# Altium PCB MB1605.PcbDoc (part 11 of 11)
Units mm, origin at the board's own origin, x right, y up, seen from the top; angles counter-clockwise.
Board outline 100 x 79.6 mm, 6 copper layers (Top Layer, Signal Layer 1, Signal Layer 2, Signal Layer 3, Signal Layer 4, Bottom Layer), stack 1.549 mm thick; 644 components, 529 nets, 2853 pads, 1462 vias.
Unrouted connection lines stored in the file: 2.
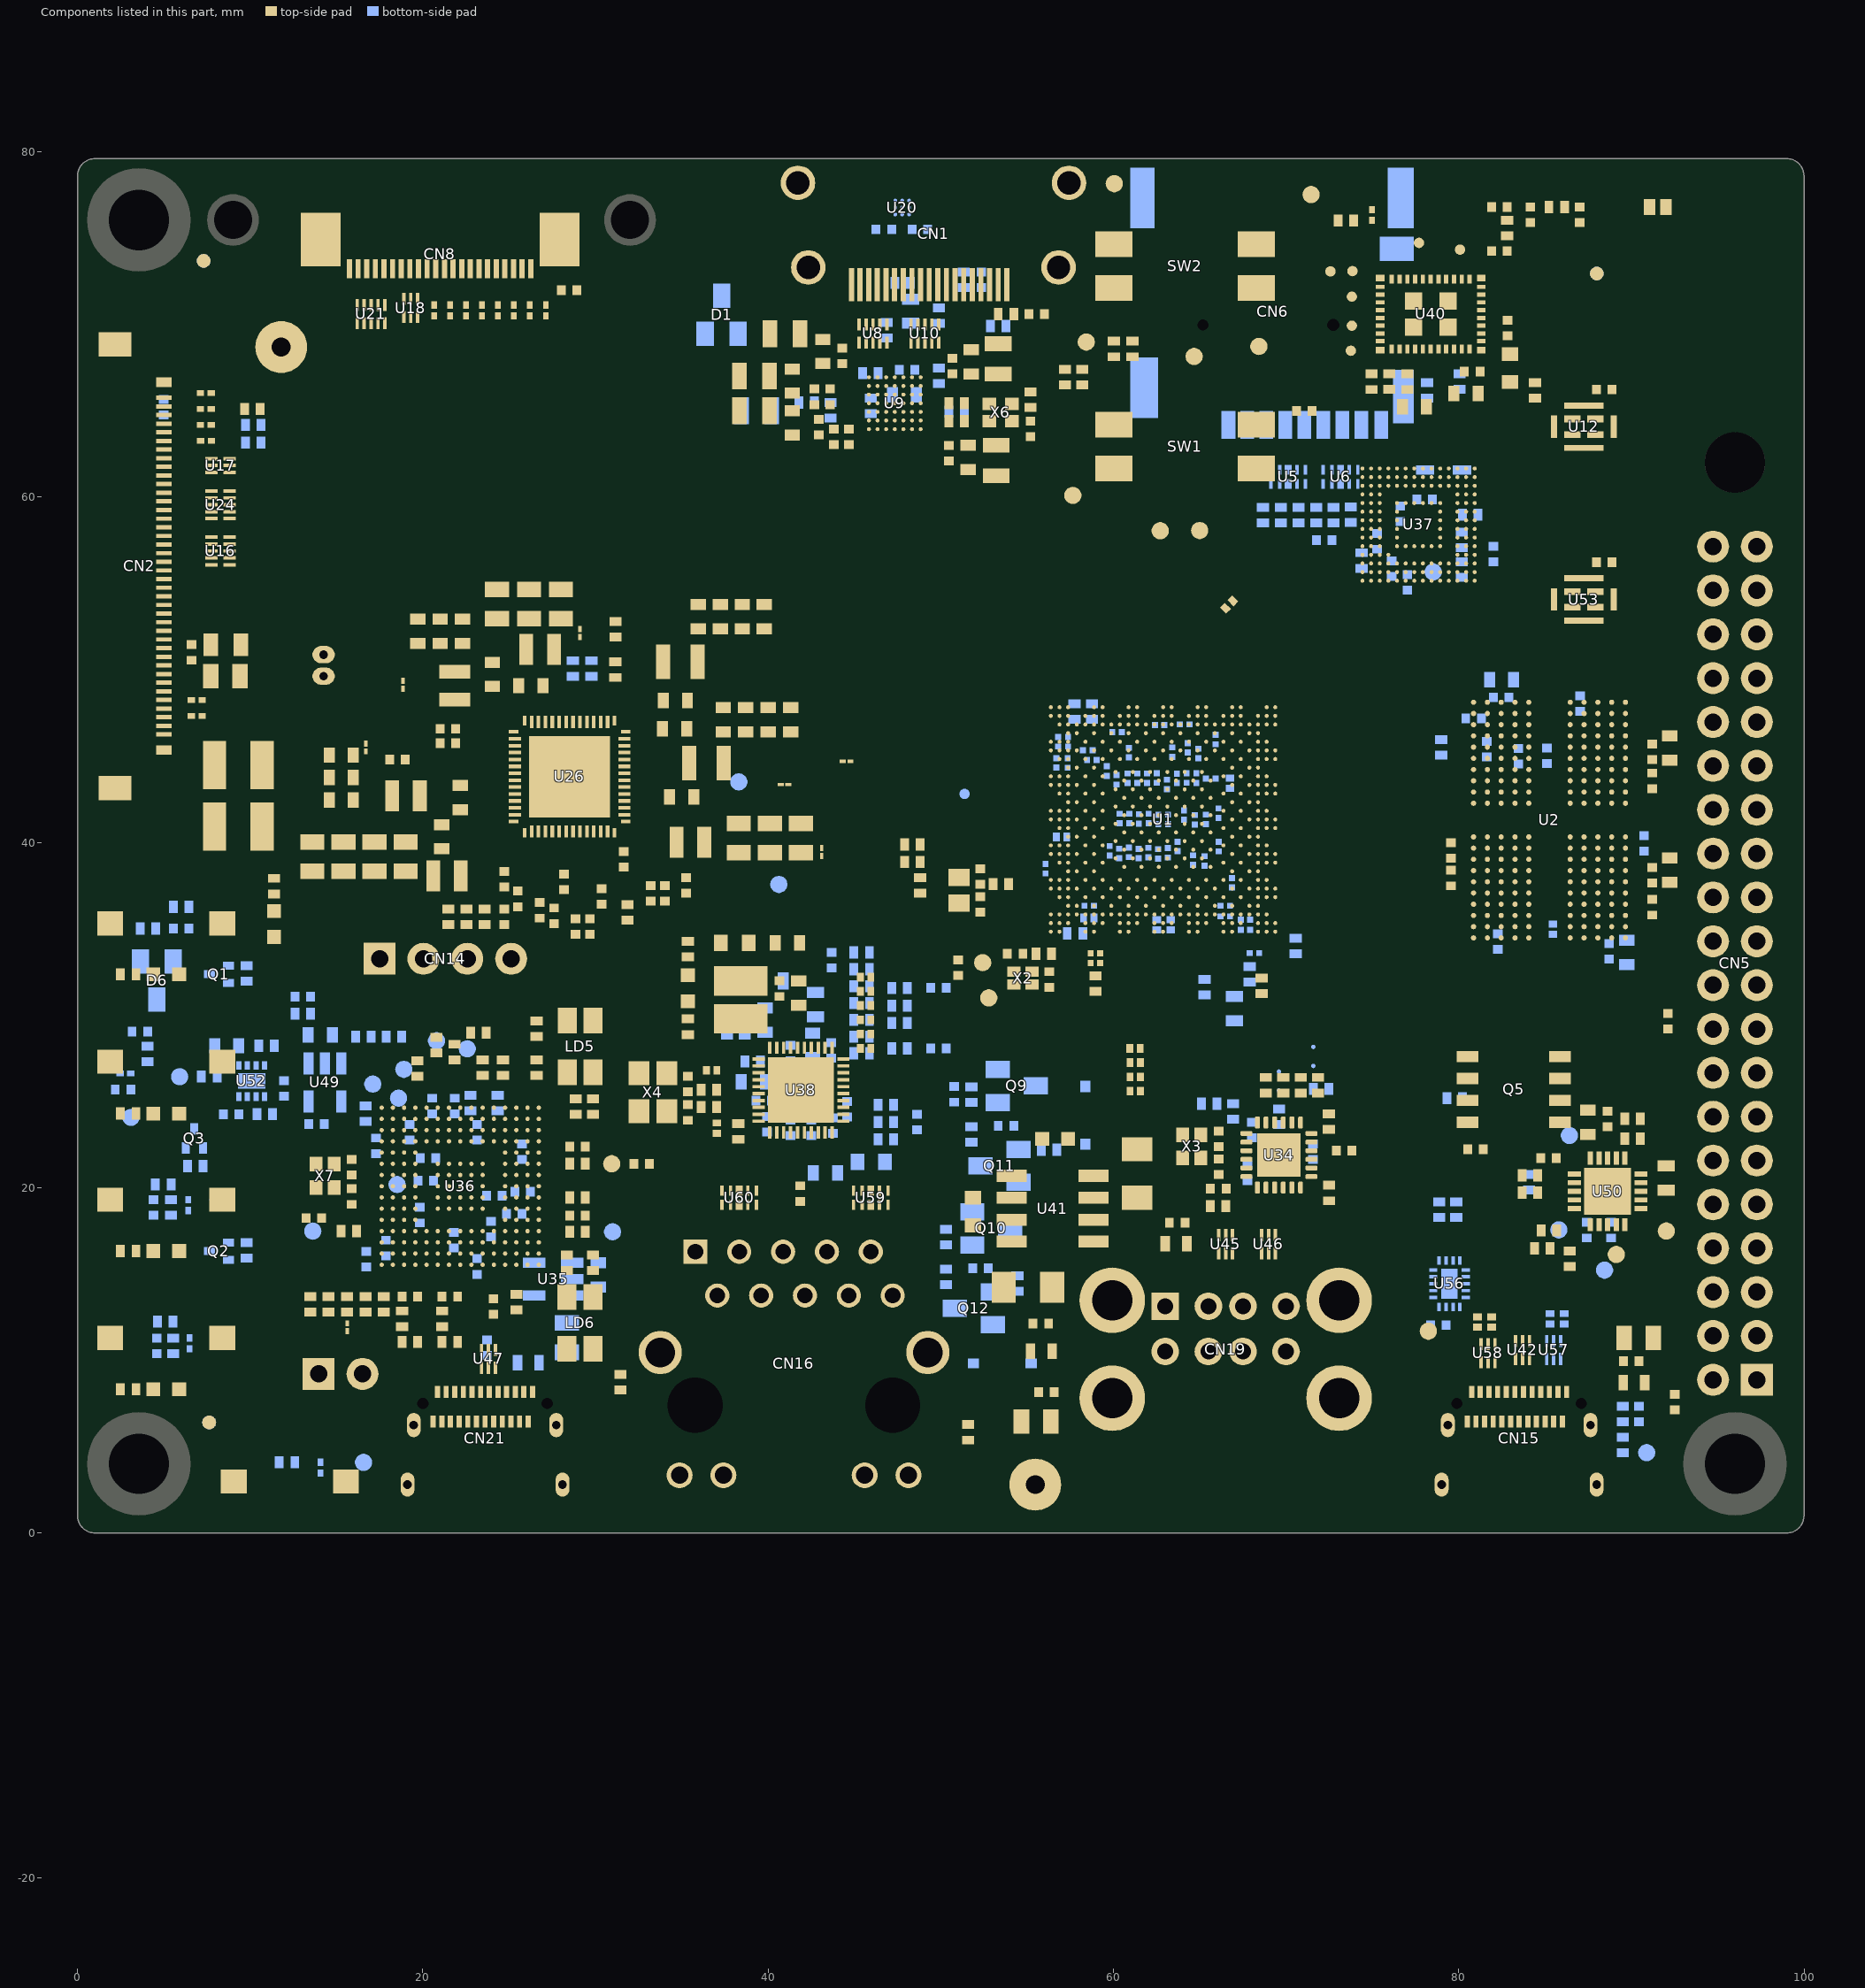
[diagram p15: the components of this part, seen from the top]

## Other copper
Top Layer:
  rectangle net 5V_STLK: 9.039,50.774 10.264,52.124
  rectangle net GND: 9.414,48.925 10.264,50.325
  rectangle net VDD2_DDR: 15.655,41.8 18.625,43.6
  region net 5V_STLK: 86.495,22.224 86.495,25.487 82.045,25.487 82.045,22.224
  region net 5V_STLK: 55.12,5.756 55.12,7.156 52.72,7.156 52.72,5.756
  region net NetL1_1: 27.572,49.875 ccw(c27.269,49.883) 27.478,50.102 27.455,50.125 27.455,50.187 27.526,50.194 ccw(c27.525,50.194) 27.525,50.195 27.675,50.075
  region net GND: 32.225,44 32.15,43.925 32.072,43.925 cw(c32.072,43.798) 32.162,43.888 32.188,43.862 ccw(c32.278,43.952) 32.278,43.825 32.947,43.825 cw(c32.947,43.698) 33.037,43.788 33.1,43.725 33.229,43.854 cw(c33.28,43.803) 33.28,43.875
  region net 5V_STLK: 33.605,47.78 33.43,47.672 ccw(c33.563,47.473) 33.394,47.642 33.353,47.601 ccw(c33.613,47.342) 33.246,47.342 33.246,47.326 ccw(c33.601,47.326) 33.35,47.075 33.35,45.539 33.349,45.538 33.347,45.551 32.876,45.08 32.27,45.08 32.27,45.345 32.506,45.345 32.98,45.819 32.98,48.347 33.308,48.67 34.325,48.67 34.325,47.78
  region net 5V_STLK: 25.23,48.524 25.131,48.425 24.775,48.425 cw(c24.775,48.775) 24.425,48.775 24.425,48.825 23.7,48.825 ccw(c23.7,48.75) 23.625,48.75 23.625,48.4 ccw(c23.827,48.397) 23.825,48.195 26.45,48.195 26.85,47.8 27.112,47.8 26.391,48.521 26.125,48.525
  region net GND: 24.9,47.685 24.807,47.685 ccw(c24.807,47.584) 24.735,47.655 24.455,47.375 ccw(c24.526,47.303) 24.425,47.303 24.425,46.975 24.925,46.975 cw(c25.323,46.982) 25.315,47.38 25.575,47.375 ccw(c25.575,47.423) 25.609,47.389 25.705,47.485
  region: 99,66.175 ccw(c99.05,66.175) 99.05,66.125 99.45,66.125 ccw(c99.45,66.175) 99.5,66.175 99.5,77.075 ccw(c99.45,77.075) 99.45,77.125 91.875,77.125 91.875,76.625 99,76.625
  pour cut-out: 90,78.05 cw(c89.925,78.05) 89.925,77.975 82.8,77.975 ccw(c82.8,76.8) 81.625,76.8 81.625,73.8 cw(c81.55,73.8) 81.55,73.725 81.075,73.725 ccw(c81.075,73.575) 80.925,73.575 80.925,71.075 ccw(c81,71.075) 81,71 81.904,71 ccw(c81.904,73.072) 83.975,73.072 83.975,75.494 cw(c84.106,75.494) 84.106,75.625 89.925,75.625 cw(c89.925,75.55) 90,75.55 90,65.6 101.05,65.6 101.05,80 90,80
  pour cut-out: 70.033,46.694 74.981,51.642 87.419,51.642 90.759,48.302 90.759,33.774 86.353,29.368 75.322,29.368 69.961,34.644
  pour cut-out: 45.292,67.365 49.286,67.365 49.286,63.578 45.292,63.578
  pour cut-out: 74.075,62 81.35,62 81.35,54.798 74.075,54.798
  pour cut-out: 80.525,48.72 90.26,48.72 90.26,34.328 80.525,34.328
  pour cut-out: 55.55,48.775 69.762,48.775 69.762,34.3 55.55,34.3
  pour cut-out: 17.29,24.95 27.025,24.95 27.025,15.175 17.29,15.175
  region net GND: 39,41.298 39,42.651 37.6,42.651 37.6,41.298
  region net GND: 40.8,41.298 40.8,42.651 39.4,42.651 39.4,41.298
  region net GND: 42.6,41.298 42.6,42.651 41.2,42.651 41.2,41.298
  pour cut-out: 40.075,31.025 40.075,30.725 36.85,30.725 36.85,31.05
  region net NetQ5_7: 82.045,25.887 82.045,28.387 91.336,28.387 93.46,26.262 93.46,20.94 91.525,20.94 91.525,22.442 91.617,22.534 91.617,24.297 90.027,25.887
  region net GND: 36.502,42.375 36.307,42.18 36,42.18 36,43.07 36.475,43.07 36.67,42.875 36.67,42.375
  region net GND: 36.325,47.975 36.13,47.78 35.275,47.78 35.275,48.67 36.13,48.67 36.325,48.475
  region net GND: 24.275,51.373 24.47,51.178 24.47,50.723 23.58,50.723 23.58,51.178 23.775,51.373
  region net GND: 36.3,46.325 36.105,46.13 35.25,46.13 35.25,47.02 36.105,47.02 36.3,46.825
  region net GND: 37.65,48.825 37.845,48.63 37.845,47.775 36.955,47.775 36.955,48.63 37.15,48.825
  region net GND: 38.95,48.825 39.145,48.63 39.145,47.775 38.255,47.775 38.255,48.63 38.45,48.825
  region net GND: 40.25,48.825 40.445,48.63 40.445,47.775 39.555,47.775 39.555,48.63 39.75,48.825
  region net GND: 41.55,48.825 41.745,48.63 41.745,47.775 40.855,47.775 40.855,48.63 41.05,48.825
  region net VDDIO: 41.58,38.835 41.58,38.719 41.227,38.366 41.227,37.235 41.58,37.235 42.22,37.235 42.577,37.235 42.577,38.431 42.22,38.788 42.22,39.212 41.58,39.212
  region net 5V_STLK: 20.075,39.948 20.725,39.948 20.725,39.305 20.42,39.305 20.325,39.4 20.075,39.4
  region net GND: 19.025,40.798 19.175,40.648 19.175,40.398 18.3,40.398 18.3,40.823 18.525,41.048 19.025,41.048
  region net GND: 19.025,40.798 18.875,40.648 18.875,40.398 19.7,40.398 19.7,40.873 19.525,41.048 19.025,41.048
  region net GND: 17.225,40.798 17.375,40.648 17.375,40.398 16.5,40.398 16.5,40.823 16.725,41.048 17.225,41.048
  region net GND: 17.225,40.798 17.075,40.648 17.075,40.398 17.9,40.398 17.9,40.873 17.725,41.048 17.225,41.048
  region net GND: 15.425,40.798 15.575,40.648 15.575,40.398 14.7,40.398 14.7,40.823 14.925,41.048 15.425,41.048
  region net GND: 15.425,40.798 15.275,40.648 15.275,40.398 16.1,40.398 16.1,40.873 15.925,41.048 15.425,41.048
  region net GND: 13.625,40.798 13.775,40.648 13.775,40.398 12.9,40.398 12.9,40.823 13.125,41.048 13.625,41.048
  region net GND: 13.625,40.798 13.475,40.648 13.475,40.398 14.3,40.398 14.3,40.873 14.125,41.048 13.625,41.048
  region net GND: 20.075,40.75 20.12,40.705 20.68,40.705 20.725,40.75 20.725,41.345 20.42,41.345 20.325,41.25 20.075,41.25
  region net 5V_STLK: 23.25,43.62 23.25,43.4 22.83,42.98 21.15,42.98 21.15,43.525 21.4,43.525 21.495,43.62
  region net GND: 21.925,40.952 21.73,41.147 21.73,41.602 22.62,41.602 22.62,41.147 22.425,40.952
  region net 5V_STLK: 27.175,49.85 27.27,49.755 27.27,49.45 26.63,49.45 26.63,49.805 26.675,49.85 26.675,50.1 27.175,50.1
  region net GND: 24.6,49.323 24.797,49.52 25.25,49.52 25.25,48.63 24.793,48.63 24.6,48.823
  region net VDD2_DDR: 16.295,45.615 16.295,45.731 16.648,46.084 16.648,47.215 16.295,47.215 15.655,47.215 15.298,47.215 15.298,46.019 15.655,45.662 15.655,45.238 16.295,45.238
  region net GND: 13.6,42.7 13.795,42.895 14.575,42.895 14.575,42.005 13.795,42.005 13.6,42.2
  region net GND: 13.6,44 13.795,44.195 14.575,44.195 14.575,43.305 13.795,43.305 13.6,43.5
  region net GND: 13.6,45.3 13.795,45.495 14.575,45.495 14.575,44.605 13.795,44.605 13.6,44.8
  region net GND: 22.55,53.873 22.745,53.678 22.745,53.223 21.855,53.223 21.855,53.678 22.05,53.873
  region net GND: 21.25,53.873 21.445,53.678 21.445,53.223 20.555,53.223 20.555,53.678 20.75,53.873
  region net GND: 19.95,53.873 20.145,53.678 20.145,53.223 19.255,53.223 19.255,53.678 19.45,53.873
  region net GND: 40.025,54.825 40.22,54.63 40.22,53.775 39.33,53.775 39.33,54.63 39.525,54.825
  region net GND: 38.75,54.825 38.945,54.63 38.945,53.775 38.055,53.775 38.055,54.63 38.25,54.825
  region net GND: 37.475,54.825 37.67,54.63 37.67,53.775 36.78,53.775 36.78,54.63 36.975,54.825
  region net GND: 36.2,54.825 36.395,54.63 36.395,53.775 35.505,53.775 35.505,54.63 35.7,54.825
  region net GND: 24.325,55.425 24.475,55.275 24.475,55.025 23.6,55.025 23.6,55.45 23.825,55.675 24.325,55.675
  region net GND: 24.325,55.425 24.175,55.275 24.175,55.025 25,55.025 25,55.5 24.825,55.675 24.325,55.675
  region net GND: 26.175,55.425 26.025,55.275 26.025,55.025 26.85,55.025 26.85,55.5 26.675,55.675 26.175,55.675
  region net GND: 26.175,55.425 26.325,55.275 26.325,55.025 25.45,55.025 25.45,55.45 25.675,55.675 26.175,55.675
  region net GND: 28.025,55.425 27.875,55.275 27.875,55.025 28.7,55.025 28.7,55.5 28.525,55.675 28.025,55.675
  region net GND: 28.025,55.425 28.175,55.275 28.175,55.025 27.3,55.025 27.3,55.45 27.525,55.675 28.025,55.675
  region net NetL2_1: 33.65,50.225 33.65,49.45 33.515,49.45 32.825,48.76 32.825,46 32.35,45.525 32.025,45.525 32.025,45.675 32.114,45.675 32.27,45.831 32.45,46.011 32.505,46.094 32.525,46.191 32.525,46.742 32.57,46.85 32.57,47.01 32.509,47.157 32.397,47.269 32.27,47.322 32.25,47.325 32.25,51.102 32.598,51.45 33.515,51.45 33.65,51.315 33.65,51.2
  region net NetL4_1: 34.525,45.6 34.525,43.6 35.434,43.6 35.434,45.6
  region net NetL3_1: 22.575,46.975 21.388,48.162 22.488,48.162 22.575,48.075 26.18,48.075 26.42,47.835 24.79,47.835 24.768,47.833 24.748,47.829 24.72,47.82 24.701,47.813 24.675,47.799 24.658,47.788 24.635,47.769 24.341,47.474 24.322,47.452 24.311,47.435 24.302,47.419 24.29,47.39 24.286,47.378 24.281,47.362 24.277,47.342 24.276,47.327 24.274,47.313 24.274,46.975
  region net NetL3_1: 23.783,48.045 23.754,48.048 23.725,48.057 23.651,48.089 23.625,48.103 23.603,48.122 23.547,48.18 23.528,48.203 23.514,48.229 23.488,48.294 23.481,48.316 23.458,48.347 23.433,48.367 23.397,48.391 23.351,48.4 22.575,48.4 22.575,47.263
  region net NetL7_1: 22.875,38.35 22.575,38.05 21.8,38.05 21.8,38.95 22.875,40.02
  region net NetL1_1: 27.995,50.275 27.65,49.93 27.195,50.385 27.195,52.075 27.995,52.075
  region net NetL5_1: 19.425,43.948 19.65,44.173 21.025,44.173 21.025,42.323 20.502,41.8 20.225,41.8 19.425,41.8
  region net 5V_STLK: 34.125,45.25 33.55,44.675 32.875,44.675 32.875,44.85 33.4,45.375
  region net GND: 32.83,44.125 33.28,44.125 33.28,43.825 33.155,43.7 32.98,43.875 32.83,43.875
  region net 5V_STLK: 34.075,41.85 33.977,41.948 33.977,42.625 34.62,42.625 34.62,41.895 34.575,41.85 34.575,41.6 34.075,41.6
  region net 5V_STLK: 34.075,41.875 34.075,42.125 33.175,43.025 33.925,43.025 34.247,42.703
  region net 5V_STLK: 34.195,46.175 34.195,45.32 34.125,45.25 34,45.375 33.4,45.375 33.555,45.53 33.555,46.175
  pour cut-out: 42.6,39.925 37.63,39.925 37.63,40.575 42.6,40.575
  pour cut-out: 12.9,38.773 19.55,38.773 19.55,39.573 12.9,39.573
  region net 5V_STLK: 34.175,49 34.325,48.85 34.325,48.6 33.525,48.6 33.525,48.85 33.675,49 33.675,49.25 34.175,49.25
  region net 5V_STLK: 23.25,49.3 23.295,49.345 23.65,49.345 23.65,48.65 23.4,48.65 23.25,48.8 23,48.8 23,49.3
  region net GND: 31.921,46.656 32.02,46.656 32.049,46.653 32.078,46.644 32.104,46.63 32.127,46.612 32.145,46.589 32.17,46.555 32.17,46.23 32.27,46.23 32.27,46.93 31.921,46.93
  region net 5V_STLK: 27.425,47.725 27.4,47.725 26.63,48.495 26.63,48.825 27.27,48.825 27.27,48.605 27.4,48.475 27.4,47.925
  region net GND: 25.575,47.375 25.24,47.375 25.24,47.385
  pour cut-out: 35.9,41.075 35.1,41.075 35.1,38.975 35.9,38.975
  pour cut-out: 36.955,45.45 35.895,45.45 35.895,43.35 36.955,43.35
  pour cut-out: 35.445,51.25 34.385,51.25 34.385,49.15 35.445,49.15
  pour cut-out: 21.94,39.1 20.88,39.1 20.88,37 21.94,37
  pour cut-out: 27.155,52.225 26.435,52.225 26.435,50.125 27.155,50.125
  pour cut-out: 20.8,49.605 20.8,48.545 22.9,48.545 22.9,49.605
  pour cut-out: 21.5,40.6 19.55,40.6 19.55,40.025 21.5,40.025
  region net 5V_STLK: 22.875,40.9 22.716,40.9 22.689,40.874 22.648,40.842 22.602,40.815 22.554,40.795 22.503,40.782 22.451,40.775 22.425,40.774 21.925,40.774 21.899,40.775 21.847,40.782 21.796,40.795 21.748,40.815 21.702,40.842 21.661,40.874 21.65,40.45 21.65,39.945 21.375,39.945 21.375,39.305 21.83,39.305 22.599,40.074 22.599,40.184 22.603,40.227 22.613,40.27 22.629,40.31 22.652,40.346 22.68,40.379 23.038,40.737
  pour cut-out: 18.495,41.65 19.555,41.65 19.555,43.75 18.495,43.75
  pour cut-out: 35.855,40.875 37.63,40.875 37.63,39.6 36.3,39.6
  region net 5V_STLK: 34.125,47.35 34.275,47.2 34.275,46.95 33.475,46.95 33.475,47.2 33.625,47.35 33.625,47.6 34.125,47.6
  text "1" at 1.614,70.692 h2
Signal Layer 1:
  text "2" at 2.9,70.692 h2
Signal Layer 2:
  text "3" at 4.406,70.703 h2
Signal Layer 3:
  text "4" at 6.769,70.694 h2
Signal Layer 4:
  text "5" at 8.249,70.713 h2
Bottom Layer:
  pour cut-out: 76.092,40.03 76.093,40.029 76.093,31.983 79.372,28.704 79.398,28.729 95.509,28.729 98.821,32.041 98.812,32.05 98.812,37.325 97.242,38.896 86.519,38.896 83.809,41.606 77.671,41.606 76.093,40.028
  region net 5V_STLK: 9.986,26.827 9.186,26.827 9.186,27.922 9.016,28.092 9.016,30.012 10.936,30.012 10.936,29.592 10.566,29.222 9.986,28.642
  region net VBUS_STLK: 10.286,22.707 10.286,23.099 9.986,23.399 9.986,25.527 9.186,25.527 9.186,23.886 8.421,23.121 8.421,22.729 9.126,22.024 9.603,22.024
  text "6" at 9.748,70.702 h2

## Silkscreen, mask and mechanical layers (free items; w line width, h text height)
Top Overlay:
  lines w0.15: 11.334,29.846 11.334,29.518 11.547,29.305 19.167,29.305 19.698,28.774 19.698,28.351 ; 35.752,26.883 35.94,27.259 ; 35.779,21.512 36.182,24.097 ; 49.675,62.725 49.675,64.55 50.025,64.9
  text "BOOT3" at 68.063,75.618 h1.2
  text "HDMI" at 36.968,75.21 h2
  text "CSI" at 29.699,72.452 h2
  text "GND" at 10.739,70.565 h1.2
  text "BOOT2" at 68.089,69.878 h1.2
  text "BOOT1" at 68.034,65.693 h1.2
  text "J" at 20.837,60.494 h15
  text "MB1605C" at 19.907,58.875 h3
  text "BOOT0" at 67.488,58.48 h1.2
  text "I" at 11.65,56.115 h15
  text "G" at 33.288,55.556 h11
  text "E" at 44.597,52.495 h12
  text "H" at 44.461,45.08 h15
  text "F" at 71.3,42.158 h12
  text "LVDS" at 1.176,40.909 h2
  text "WAKE UP" at 1.063,37.75 h2
  text "RESERVED" at 15.964,30.434 h2
  text "TAMPER" at 1.34,29.563 h2
  text "C" at 70.691,29.487 h11
  text "COM" at 32.263,28.177 h2 r90
  text "USER2" at 2.272,21.666 h2
  text "USER1" at 2.142,13.697 h2
  text "PWR" at 32.19,10.17 h2 r90
  text "RESET" at 9.548,5.243 h2
  text "GND" at 53.71,1.714 h1.2 r90
  text "USB" at 59.366,1.505 h2 r90
  text "ETH" at 51.79,1.405 h2 r90
  text "USB DRD" at 78.165,0.395 h2 r90
  text "USB PWR / STLNK" at 31.533,0.355 h2 r90
Bottom Overlay:
  lines w0.15: 57.925,42.3 58.15,42.525 58.15,44.475
Top Solder:
  region: 1.325,72.334 1.325,70.334 10.075,70.334 10.075,72.334
Bottom Solder:
  region: 1.325,72.334 1.325,70.334 10.075,70.334 10.075,72.334
M1-Board Shape:
  the board outline again, w0.02
Drill Drawing:
  drawing of 358 lines, arcs and shapes, not listed
  text "Layer" at 122.2,127.475 h2
  text "Name" at 130.567,127.475 h2
  text "Material" at 146.741,127.475 h2
  text "Thickness" at 161.275,127.475 h2
  text "Constant" at 173.215,127.475 h2
  text "PCB SPECIFICATIONS :" at -27.02,127.275 h3
  text "Top Overlay" at 130.567,123.475 h2
  text "A.   MATERIAL :" at -27.02,123.275 h3
  text "FR-4" at 11.48,123.275 h3
  text "TG-170" at 27.98,123.275 h3
  text "X  TG-150" at 46.23,123.275 h3
  text "TG-140" at 62.23,123.275 h3
  text "B.   MATERIAL FAMILY :" at -27.02,120.275 h3
  text "N/A" at 11.48,120.275 h3
  text "Top Solder" at 130.567,119.475 h2
  text "Solder Resist" at 146.741,119.475 h2
  text "0,025mm" at 161.275,119.475 h2
  text "3.5" at 173.215,119.475 h2
  text "C.   SOLDERMASK COLOR :" at -27.02,117.275 h3
  text "GREEN" at 11.48,117.275 h3
  text "X  BLUE" at 27.98,117.275 h3
  text "RED" at 46.23,117.275 h3
  text "BLACK" at 62.23,117.275 h3
  text "1" at 122.2,115.475 h2
  text "Top Layer" at 130.567,115.475 h2
  text "0,037mm" at 161.275,115.475 h2
  text "D.   SILKSCREEN COLOR :" at -27.02,114.275 h3
  text "X  WHITE" at 11.48,114.275 h3
  text "YELLOW" at 27.98,114.275 h3
  text "BLACK" at 46.23,114.275 h3
  text "PCB : TYPE 4" at 187.138,113.471 h3
  text "Dielectric 1" at 130.567,111.475 h2
  text "0,072mm" at 161.275,111.475 h2
  text "3.8" at 173.215,111.475 h2
  text "E.   SURFACE FINISH :" at -27.02,111.275 h3
  text "X  ENIG" at 11.48,111.275 h3
  text "IMMERSION SILVER" at 27.98,111.275 h3
  text "IMMERSION TIN" at 62.23,111.275 h3
  text "HASL" at 11.48,108.275 h3
  text "HASL (PB-FREE)" at 27.98,108.275 h3
  text "GOLDEN FINGER" at 62.23,108.275 h3
  text "ASPECT-RATIO, AXE Z :" at 187.138,107.971 h3
  text "2" at 122.199,107.475 h2
  text "Signal Layer 1" at 130.567,107.475 h2
  text "0,035mm" at 161.275,107.475 h2
  text "F.   IMPEDANCE CONTROL :" at -27.02,105.275 h3
  text "NO" at 11.48,105.275 h3
  text "X  YES" at 27.98,105.275 h3
  text "Dielectric 2" at 130.567,103.475 h2
  text "0,500mm" at 161.275,103.475 h2
  text "5" at 173.215,103.475 h2
  text "G.   THROUGH VIA :" at -27.02,102.275 h3
  text "PLUG THE VIAS WHICH ARE COVERED WITH SOLDERMASK ONE OR TWO SIDE." at 11.48,102.275 h3
  text "6 :1  to  8 :1 / LEVEL \"B\"" at 187.157,101.224 h3
  text "3" at 122.2,99.475 h2
  text "Signal Layer 2" at 130.567,99.475 h2
  text "0,035mm" at 161.275,99.475 h2
  text "PLUG MATERIAL :" at 11.48,99.275 h3
  text "X  SOLDERMASK" at 36.98,99.275 h3
  text "NON-CONDUCTIVE EPOXY." at 62.23,99.275 h3
  text "H.   STACK-UP :" at -27.02,96.275 h3
  text "SEE LAYER STACK-UP SEQUENCE FOR OVERALL THICKNESS." at 11.48,96.275 h3
  text "Dielectric 3" at 130.567,95.475 h2
  text "0,191mm" at 161.275,95.475 h2
  text "4.3" at 173.215,95.475 h2
  text "4" at 122.2,91.475 h2
  text "Signal Layer 3" at 130.567,91.475 h2
  text "0,035mm" at 161.275,91.475 h2
  text "MINIMUN PARAMETERS" at 187.25,89.695 h3
  text "Dielectric 4" at 130.567,87.475 h2
  text "0,500mm" at 161.275,87.475 h2
  text "5" at 173.215,87.475 h2
  text "DEFAULT" at 187.25,84.195 h3
  text "5" at 122.2,83.475 h2
  text "Signal Layer 4" at 130.567,83.475 h2
  text "0,035mm" at 161.275,83.475 h2
  text "Dielectric 5" at 130.567,79.475 h2
  text "0,072mm" at 161.275,79.475 h2
  text "3.8" at 173.215,79.475 h2
  text "TRACKS : 0.100mm           / GAPS : 0.100mm" at 187.25,78.445 h3
  text "6" at 122.2,75.475 h2
  text "Bottom Layer" at 130.567,75.475 h2
  text "0,037mm" at 161.275,75.475 h2
  text "BGA :" at 187.225,73.62 h3
  text "Bottom Solder" at 130.567,71.475 h2
  text "Solder Resist" at 146.741,71.475 h2
  text "0,025mm" at 161.275,71.475 h2
  text "3.5" at 173.215,71.475 h2
  text "TRACKS : 0.090mm           / GAPS : 0.090mm" at 187.225,67.87 h3
  text "Bottom Overlay" at 130.567,67.475 h2
  text "Symbol" at 108.266,55.347 h2.4
  text "Count" at 117.663,55.347 h2.4
  text "Hole Size" at 128.274,55.347 h2.4
  text "Plated" at 139.687,55.347 h2.4
  text "Hole Type" at 147.939,55.347 h2.4
  text "Drill Layer Pair" at 159.949,55.347 h2.4
  text "Via/Pad" at 183.129,55.347 h2.4
  text "Pad Shape" at 192.971,55.347 h2.4
  text "Hole Length" at 205.83,55.347 h2.4
  text "29" at 117.663,51.208 h2
  text "0,100mm" at 128.274,51.208 h2
  text "PTH" at 139.687,51.208 h2
  text "Round" at 147.939,51.208 h2
  text "Top Layer - Signal Layer 1" at 159.949,51.208 h2
  text "Via" at 183.129,51.208 h2
  text "Rounded" at 192.971,51.208 h2
  text "-" at 205.83,51.208 h2
  text "E" at 107.478,50.954 h1.84
  text "610" at 117.663,47.068 h2
  text "0,200mm" at 128.274,47.068 h2
  text "PTH" at 139.687,47.068 h2
  text "Round" at 147.939,47.068 h2
  text "Top Layer - Bottom Layer" at 159.949,47.068 h2
  text "Via" at 183.129,47.068 h2
  text "Rounded" at 192.971,47.068 h2
  text "-" at 205.83,47.068 h2
  text "D" at 107.478,46.814 h1.84
  text "823" at 117.663,42.928 h2
  text "0,350mm" at 128.274,42.928 h2
  text "PTH" at 139.687,42.928 h2
  text "Round" at 147.939,42.928 h2
  text "Top Layer - Bottom Layer" at 159.949,42.928 h2
  text "Via" at 183.129,42.928 h2
  text "Rounded" at 192.971,42.928 h2
  text "-" at 205.83,42.928 h2
  text "C" at 107.478,42.675 h1.84
  text "2" at 117.663,38.788 h2
  text "0,500mm" at 128.274,38.788 h2
  text "PTH" at 139.687,38.788 h2
  text "Round" at 147.939,38.788 h2
  text "Top Layer - Bottom Layer" at 159.949,38.788 h2
  text "Pad" at 183.129,38.788 h2
  text "Rounded" at 192.971,38.788 h2
  text "-" at 205.83,38.788 h2
  text "8" at 117.663,34.649 h2
  text "0,500mm" at 128.274,34.649 h2
  text "PTH" at 139.687,34.649 h2
  text "Slot" at 147.939,34.649 h2
  text "Top Layer - Bottom Layer" at 159.949,34.649 h2
  text "Pad" at 183.129,34.649 h2
  text "Rounded" at 192.971,34.649 h2
  text "1,100mm" at 205.83,34.649 h2
  text "3" at 117.663,30.509 h2
  text "0,650mm" at 128.274,30.509 h2
  text "NPTH" at 139.687,30.509 h2
  text "Round" at 147.939,30.509 h2
  text "Top Layer - Bottom Layer" at 159.949,30.509 h2
  text "Pad" at 183.129,30.509 h2
  text "Rounded" at 192.971,30.509 h2
  text "-" at 205.83,30.509 h2
  text "2" at 117.663,26.369 h2
  text "0,650mm" at 128.274,26.369 h2
  text "NPTH" at 139.687,26.369 h2
  text "Slot" at 147.939,26.369 h2
  text "Top Layer - Bottom Layer" at 159.949,26.369 h2
  text "Pad" at 183.129,26.369 h2
  text "Rounded" at 192.971,26.369 h2
  text "0,950mm" at 205.83,26.369 h2
  text "1" at 117.663,22.23 h2
  text "0,700mm" at 128.274,22.23 h2
  text "NPTH" at 139.687,22.23 h2
  text "Round" at 147.939,22.23 h2
  text "Top Layer - Bottom Layer" at 159.949,22.23 h2
  text "Pad" at 183.129,22.23 h2
  text "Rounded" at 192.971,22.23 h2
  text "-" at 205.83,22.23 h2
  text "10" at 117.663,18.09 h2
  text "0,900mm" at 128.274,18.09 h2
  text "PTH" at 139.687,18.09 h2
  text "Round" at 147.939,18.09 h2
  text "Top Layer - Bottom Layer" at 159.949,18.09 h2
  text "Pad" at 183.129,18.09 h2
  text "(Mixed)" at 192.971,18.09 h2
  text "-" at 205.83,18.09 h2
  text "8" at 117.663,13.95 h2
  text "0,920mm" at 128.274,13.95 h2
  text "PTH" at 139.687,13.95 h2
  text "Round" at 147.939,13.95 h2
  text "Top Layer - Bottom Layer" at 159.949,13.95 h2
  text "Pad" at 183.129,13.95 h2
  text "(Mixed)" at 192.971,13.95 h2
  text "-" at 205.83,13.95 h2
  text "A" at 107.478,13.696 h1.84
  text "50" at 117.663,9.81 h2
  text "1,000mm" at 128.274,9.81 h2
  text "PTH" at 139.687,9.81 h2
  text "Round" at 147.939,9.81 h2
  text "Top Layer - Bottom Layer" at 159.949,9.81 h2
  text "Pad" at 183.129,9.81 h2
  text "Rounded" at 192.971,9.81 h2
  text "-" at 205.83,9.81 h2
  text "2" at 117.663,5.671 h2
  text "1,100mm" at 128.274,5.671 h2
  text "PTH" at 139.687,5.671 h2
  text "Round" at 147.939,5.671 h2
  text "Top Layer - Bottom Layer" at 159.949,5.671 h2
  text "Pad" at 183.129,5.671 h2
  text "Rounded" at 192.971,5.671 h2
  text "-" at 205.83,5.671 h2
  text "4" at 117.663,1.531 h2
  text "1,350mm" at 128.274,1.531 h2
  text "PTH" at 139.687,1.531 h2
  text "Round" at 147.939,1.531 h2
  text "Top Layer - Bottom Layer" at 159.949,1.531 h2
  text "Pad" at 183.129,1.531 h2
  text "Rounded" at 192.971,1.531 h2
  text "-" at 205.83,1.531 h2
  text "2" at 117.663,-2.609 h2
  text "1,700mm" at 128.274,-2.609 h2
  text "PTH" at 139.687,-2.609 h2
  text "Round" at 147.939,-2.609 h2
  text "Top Layer - Bottom Layer" at 159.949,-2.609 h2
  text "Pad" at 183.129,-2.609 h2
  text "Rounded" at 192.971,-2.609 h2
  text "-" at 205.83,-2.609 h2
  text "2" at 117.663,-6.748 h2
  text "2,200mm" at 128.274,-6.748 h2
  text "PTH" at 139.687,-6.748 h2
  text "Round" at 147.939,-6.748 h2
  text "Top Layer - Bottom Layer" at 159.949,-6.748 h2
  text "Pad" at 183.129,-6.748 h2
  text "Rounded" at 192.971,-6.748 h2
  text "-" at 205.83,-6.748 h2
  text "4" at 117.663,-10.888 h2
  text "2,330mm" at 128.274,-10.888 h2
  text "PTH" at 139.687,-10.888 h2
  text "Round" at 147.939,-10.888 h2
  text "Top Layer - Bottom Layer" at 159.949,-10.888 h2
  text "Pad" at 183.129,-10.888 h2
  text "Rounded" at 192.971,-10.888 h2
  text "-" at 205.83,-10.888 h2
  text "B" at 107.478,-11.142 h1.84
  text "2" at 117.663,-15.028 h2
  text "3,200mm" at 128.274,-15.028 h2
  text "NPTH" at 139.687,-15.028 h2
  text "Round" at 147.939,-15.028 h2
  text "Top Layer - Bottom Layer" at 159.949,-15.028 h2
  text "Pad" at 183.129,-15.028 h2
  text "Rounded" at 192.971,-15.028 h2
  text "-" at 205.83,-15.028 h2
  text "1" at 117.663,-19.168 h2
  text "3,500mm" at 128.274,-19.168 h2
  text "NPTH" at 139.687,-19.168 h2
  text "Round" at 147.939,-19.168 h2
  text "Top Layer - Bottom Layer" at 159.949,-19.168 h2
  text "Pad" at 183.129,-19.168 h2
  text "Rounded" at 192.971,-19.168 h2
  text "-" at 205.83,-19.168 h2
  text "3" at 117.663,-23.307 h2
  text "3,500mm" at 128.274,-23.307 h2
  text "PTH" at 139.687,-23.307 h2
  text "Round" at 147.939,-23.307 h2
  text "Top Layer - Bottom Layer" at 159.949,-23.307 h2
  text "Pad" at 183.129,-23.307 h2
  text "Rounded" at 192.971,-23.307 h2
  text "-" at 205.83,-23.307 h2
  text "1566 Total" at 117.663,-27.447 h2
  text "Slot definitions :" at 108.266,-30.345 h2
  text "Routed Path Length" at 121.888,-30.345 h2
  text "= Calculated from tool start centre position to tool end centre position." at 138.771,-30.345 h2
  text "Hole Length" at 121.888,-32.001 h2
  text "= Routed Path Length + Tool Size = Slot length as defined in the PCB layout" at 132.504,-32.001 h2

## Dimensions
1,79.6 to 1,0 on M2-Board Dimensions
0,78.6 to 100,78.6 on M2-Board Dimensions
